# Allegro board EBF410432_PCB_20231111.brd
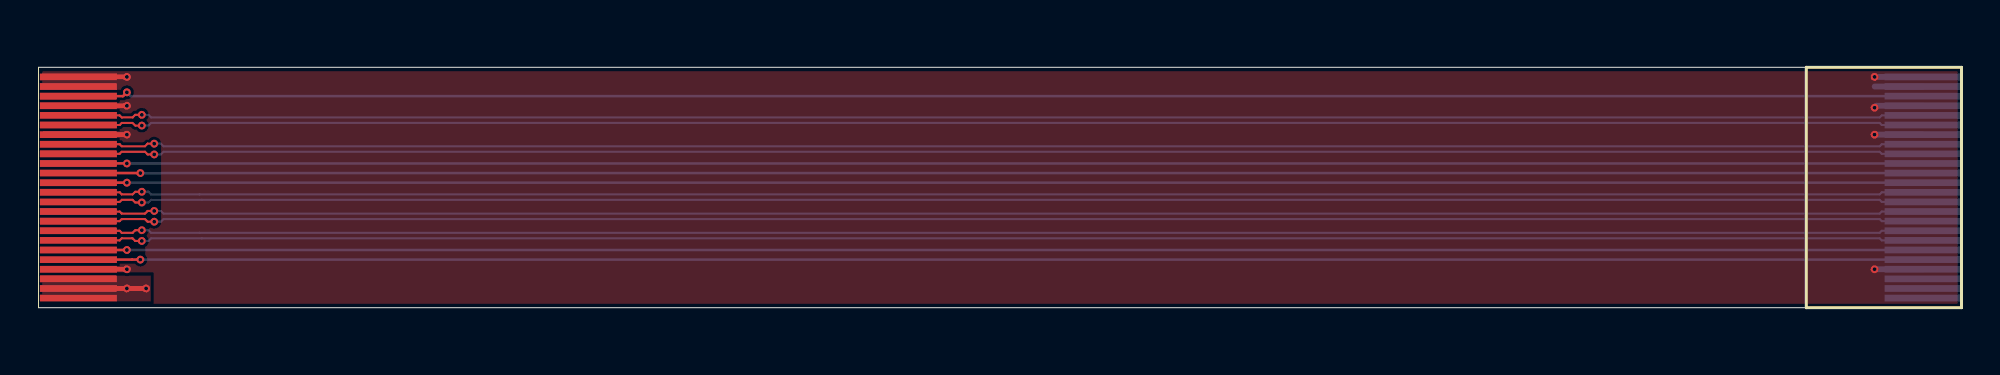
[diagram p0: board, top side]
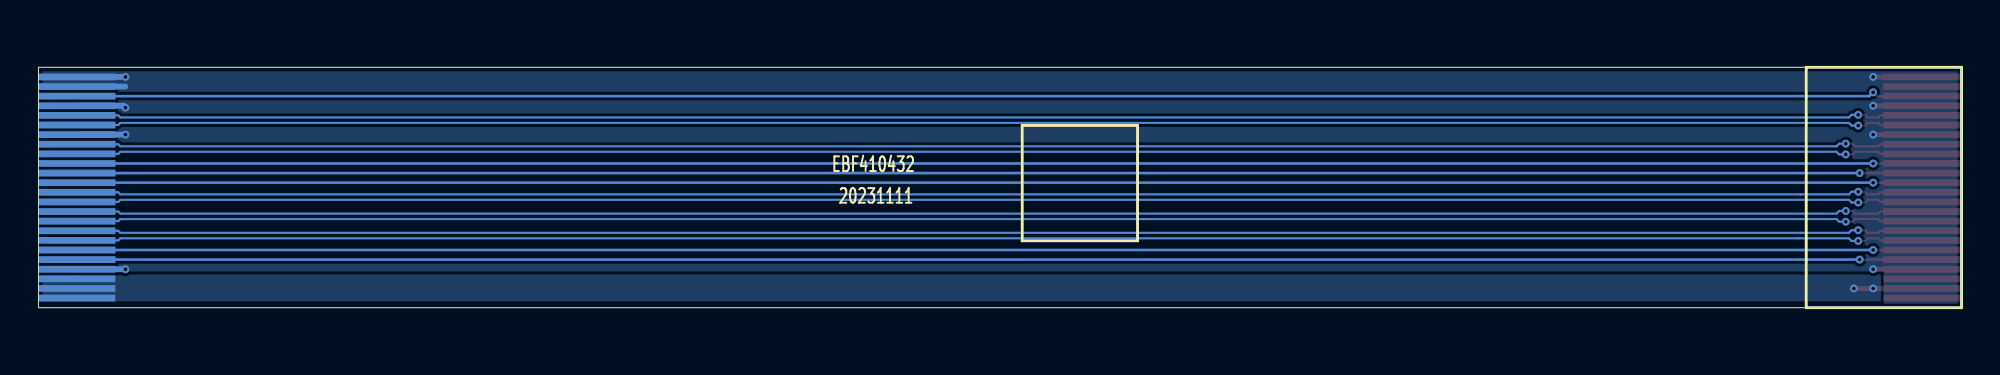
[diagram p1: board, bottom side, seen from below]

Outline 100 x 12.5 mm; copper layers: TOP, GND02, GND03, BOTTOM. Coordinates in mm from the lower left corner of the outline.
Outline path: 0,12.5 0,0 100,0 100,12.5 0,12.5

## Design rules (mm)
net group MIPI_CSI_CLK: nets MIPI_CSI_CLKN MIPI_CSI_CLKP
net group MIPI_CSI_D0: nets MIPI_CSI_D0N MIPI_CSI_D0P
net group MIPI_CSI_D1: nets MIPI_CSI_D1N MIPI_CSI_D1P
net group MIPI_CSI_D2: nets MIPI_CSI_D2N MIPI_CSI_D2P
net group MIPI_CSI_D3: nets MIPI_CSI_D3N MIPI_CSI_D3P

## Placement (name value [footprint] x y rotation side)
J1  24PIN_FPC  [FPC24-0R50]  98 6.25 90 bottom
J2  24PIN_FPC  [FPC24-0R50]  2.07 6.25 90 top
NOREF  -  []  0 0 90 top
NOREF#2  -  []  45.85 6.48 0 top
NOREF#3  -  []  0 0 0 top

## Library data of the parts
J1 J2 = 24PIN_FPC

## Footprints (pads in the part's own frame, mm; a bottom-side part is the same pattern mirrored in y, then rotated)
FPC24-0R50
  rect 0.35x4 smd: 1(-5.75,0) 2(-5.25,0) 3(-4.75,0) 4(-4.25,0) 5(-3.75,0) 6(-3.25,0) 7(-2.75,0) 8(-2.25,0) 9(-1.75,0) 10(-1.25,0) 11(-0.75,0) 12(-0.25,0) 13(0.25,0) 14(0.75,0) 15(1.25,0) 16(1.75,0) 17(2.25,0) 18(2.75,0) 19(3.25,0) 20(3.75,0) 21(4.25,0) 22(4.75,0) 23(5.25,0) 24(5.75,0)

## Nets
GND: J1.4 J1.18 J1.21 J1.23 J1.24 J2.4 J2.18 J2.21 J2.23 J2.24
VCC_CAM_5V0: J1.1 J1.2 J1.3 J2.1 J2.2 J2.3
CAM_NRST: J1.22 J2.22
CAM_PWDN: J1.15 J2.15
I2C_SCL: J1.6 J2.6
I2C_SDA: J1.5 J2.5
MIPI_CSI_CLKN: J1.10 J2.10
MIPI_CSI_CLKP: J1.9 J2.9
MIPI_CSI_D0N: J1.12 J2.12
MIPI_CSI_D0P: J1.11 J2.11
MIPI_CSI_D1N: J1.8 J2.8
MIPI_CSI_D1P: J1.7 J2.7
MIPI_CSI_D2N: J1.17 J2.17
MIPI_CSI_D2P: J1.16 J2.16
MIPI_CSI_D3N: J1.20 J2.20
MIPI_CSI_D3P: J1.19 J2.19
RESERVED1: J1.13 J2.13
RESERVED2: J1.14 J2.14

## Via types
v1: diameter 0.406, hole 0.203, TOP to BOTTOM, 26 vias

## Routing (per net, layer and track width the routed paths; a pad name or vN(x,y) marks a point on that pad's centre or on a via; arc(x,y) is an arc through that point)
GND: length 22.7
  TOP w0.254: J2.21 v1(4.6,10.5) ; J2.18 v1(4.6,9) ; J2.24 v1(4.6,12) ; J2.4 v1(4.6,2)
  BOTTOM w0.305: J1.21 95.58,10.5 v1(95.48,10.4) ; J1.23 95.48,11.5 ; J1.4 v1(95.48,2) ; J1.18 v1(95.48,9) ; J1.24 v1(95.48,12)
VCC_CAM_5V0: length 3.5
  TOP w0.254: J2.2 v1(4.6,1) v1(5.6,1)
CAM_NRST: length 96.1
  TOP w0.132: v1(4.6,11.2) 4.4,11 J2.22
  BOTTOM w0.132: J1.22 4.8,11 v1(4.6,11.2)
CAM_PWDN: length 95.9
  TOP w0.132: J2.15 v1(4.6,7.5)
  BOTTOM w0.132: v1(4.6,7.5) J1.15
I2C_SCL: length 95.9
  TOP w0.132: J2.6 v1(4.6,3)
  BOTTOM w0.132: J1.6 v1(4.6,3)
I2C_SDA: length 95.9
  TOP w0.132: J2.5 4.88,2.5 v1(5.3,2.5)
  BOTTOM w0.132: v1(5.3,2.5) J1.5
MIPI_CSI_CLKN: length 96.1
  TOP w0.107: v1(6.02,5.03) 5.67,5.03 5.54,4.89 4.33,4.89 4.22,5 J2.10
  BOTTOM w0.107: J1.10 95.85,5 95.74,4.89 6.5,4.89 6.36,5.03 v1(6.02,5.03)
MIPI_CSI_CLKP: length 96.1
  TOP w0.107: v1(6.02,4.47) 5.67,4.47 5.54,4.61 4.33,4.61 4.22,4.5 J2.9
  BOTTOM w0.107: J1.9 95.85,4.5 95.74,4.61 6.5,4.61 6.36,4.47 v1(6.02,4.47)
MIPI_CSI_D0N: length 96.1
  TOP w0.107: v1(5.37,6.03) 5.03,6.03 4.89,5.89 4.33,5.89 4.22,6 J2.12
  BOTTOM w0.107: J1.12 95.85,6 95.74,5.89 8.38,5.89 5.86,5.89 5.72,6.03 v1(5.37,6.03)
MIPI_CSI_D0P: length 96.1
  TOP w0.107: v1(5.37,5.47) 5.03,5.47 4.89,5.61 4.33,5.61 4.22,5.5 J2.11
  BOTTOM w0.107: J1.11 95.85,5.5 95.74,5.61 8.49,5.61 5.86,5.61 5.72,5.47 v1(5.37,5.47)
MIPI_CSI_D1N: length 96.1
  TOP w0.107: J2.8 4.22,4 4.33,3.89 4.89,3.89 5.03,4.03 v1(5.37,4.03)
  BOTTOM w0.107: v1(5.37,4.03) 5.72,4.03 5.86,3.89 8.38,3.89 95.74,3.89 95.85,4 J1.8
MIPI_CSI_D1P: length 96.1
  TOP w0.107: J2.7 4.22,3.5 4.33,3.61 4.89,3.61 5.03,3.47 v1(5.37,3.47)
  BOTTOM w0.107: J1.7 95.85,3.5 95.74,3.61 8.49,3.61 5.86,3.61 5.72,3.47 v1(5.37,3.47)
MIPI_CSI_D2N: length 96.1
  TOP w0.107: J2.17 4.22,8.5 4.33,8.39 5.54,8.39 5.67,8.53 v1(6.02,8.53)
  BOTTOM w0.107: J1.17 95.85,8.5 95.74,8.39 6.5,8.39 6.36,8.53 v1(6.02,8.53)
MIPI_CSI_D2P: length 96.1
  TOP w0.107: v1(6.02,7.97) 5.67,7.97 5.54,8.11 4.33,8.11 4.22,8 J2.16
  BOTTOM w0.107: J1.16 95.85,8 95.74,8.11 6.5,8.11 6.36,7.97 v1(6.02,7.97)
MIPI_CSI_D3N: length 96.1
  TOP w0.107: v1(5.37,10.03) 5.03,10.03 4.89,9.89 4.33,9.89 4.22,10 J2.20
  BOTTOM w0.107: v1(5.37,10.03) 5.72,10.03 5.86,9.89 95.74,9.89 95.85,10 J1.20
MIPI_CSI_D3P: length 96.1
  TOP w0.107: v1(5.37,9.47) 5.03,9.47 4.89,9.61 4.33,9.61 4.22,9.5 J2.19
  BOTTOM w0.107: J1.19 95.85,9.5 95.74,9.61 5.86,9.61 5.72,9.47 v1(5.37,9.47)
RESERVED1: length 95.9
  TOP w0.132: J2.13 v1(4.6,6.5)
  BOTTOM w0.132: v1(4.6,6.5) J1.13
RESERVED2: length 95.9
  TOP w0.132: J2.14 v1(5.3,7)
  BOTTOM w0.132: v1(5.3,7) J1.14

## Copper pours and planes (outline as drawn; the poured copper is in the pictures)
GND on TOP: 0.2,0.2 0.2,12.3 99.8,12.3 99.8,0.2 ; 2 cut-outs
GND on BOTTOM: 0.2,0.2 0.2,12.3 99.8,12.3 99.8,0.2 ; 5 cut-outs
GND on GND02, GND03: 0.2,0.2 0.2,12.3 99.8,12.3 99.8,0.2
VCC_CAM_5V0 on TOP: 0.2,0.33 0.2,1.68 5.84,1.68 5.84,0.33
VCC_CAM_5V0 on BOTTOM: 4.19,0.33 4.19,1.73 99.8,1.73 99.8,0.33

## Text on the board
Ref Des/Silkscreen Bottom: 20231111 | EBF410432
DIMENSION: FIGURE | SIZE | 8.0 | DRILL CHART: TOP to BOTTOM | ALL UNITS ARE IN MILS | PLATED | QTY | 26
